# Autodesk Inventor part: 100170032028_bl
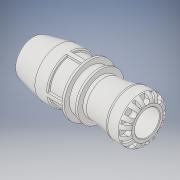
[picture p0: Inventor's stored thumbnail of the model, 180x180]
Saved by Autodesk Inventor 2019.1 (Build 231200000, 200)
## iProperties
Created: 2016-12
Part Number: 100170032028_bl
Material: PVC-Piping
Description: PLASSON UNIVERSAL COUPLING 24-28X32 SERIES 1
Document SubType Name: Modeling
Designer: KIM
Mass: 298.996 g
Surface Area: 569.061 cm^2
Volume: 213.568 cm^3
Density: 1.4 g/cm^3
Appearance: Smooth - White
Author: KIM
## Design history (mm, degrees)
derived "10017.ipt"
feature "Solid1::10017.ipt" dims "ScaleForDerivedMember" = 10
tag "TaggingFeature1"
body "Solid1"
other parameters: "d15" = 28 [user parameter], "d16" = 27.44 [user parameter], "d20" = 54.12 [user parameter], "d21" = 80 deg [user parameter], "d22" = 21 [user parameter], "d23" = 0 [user parameter], "d25" = 360 deg [user parameter], "d48" = 1.6 [user parameter], "d52" = 0.66 [user parameter], "d72" = 32 [user parameter], "d73" = 55 [user parameter], "d74" = 3.2 [user parameter], "d80" = 23.1 [user parameter], "d81" = 77 deg [user parameter], "d82" = 147 [user parameter], "d83" = 73.5 [user parameter], "d84" = 55 [user parameter], "d85" = 3.66667 [user parameter], "d86" = 66 [user parameter], "d87" = 60.72 [user parameter], "d88" = 57.6 [user parameter], "d89" = 11 [user parameter], "d90" = 52.8 [user parameter], "d91" = 46.08 [user parameter], "d93" = 1.47 [user parameter], "d96" = 7.04 [user parameter], "d97" = 7.04 [user parameter], "d98" = 0 [user parameter], "d100" = 360 deg [user parameter], "d103" = 0.64 [user parameter], "d104" = 0.64 [user parameter], "d105" = 8 deg [user parameter], "d106" = 8 deg [user parameter], "d108" = 0 [user parameter], "d110" = 360 deg [user parameter], "d112" = 9.6 [user parameter], "d113" = 4.8 [user parameter], "d115" = 44 [user parameter], "d116" = 0 [user parameter], "d118" = 360 deg [user parameter], "d120" = 6.6 [user parameter], "d121" = 0.66 [user parameter], "d_" = 32 [user parameter], "E_" = 66 [user parameter], "H_" = 147 [user parameter], "l_" = 55 [user parameter], "d_1" = 28 [user parameter], "l_1" = 55 [user parameter], "d66" = 76 [user parameter], "d68" = 41 [user parameter], "d69" = 45 [user parameter], "d70" = 20.955 [user parameter], "d71" = 13 [user parameter], "d92" = 8.8 [user parameter], "d94" = 57.6 [user parameter]
